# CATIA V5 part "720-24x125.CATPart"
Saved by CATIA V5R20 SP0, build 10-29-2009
Part number: 720-24x125
Definition: NONE
Nomenclature: 720-24x125
Source: Unknown
Description: 720-24x125
Bounding box of the stored display mesh (mm): x 0 to 125, y -12 to 12, z -12 to 12
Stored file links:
  C:\Users\Utente\Desktop\IO LAVORO\3D X SITO CF\X SITO\720\720-24x125.CATPart
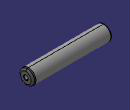
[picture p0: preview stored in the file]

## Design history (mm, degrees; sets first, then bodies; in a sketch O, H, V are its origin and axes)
Body1 "720-24x125" (main body)
  Solid1: solid without history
